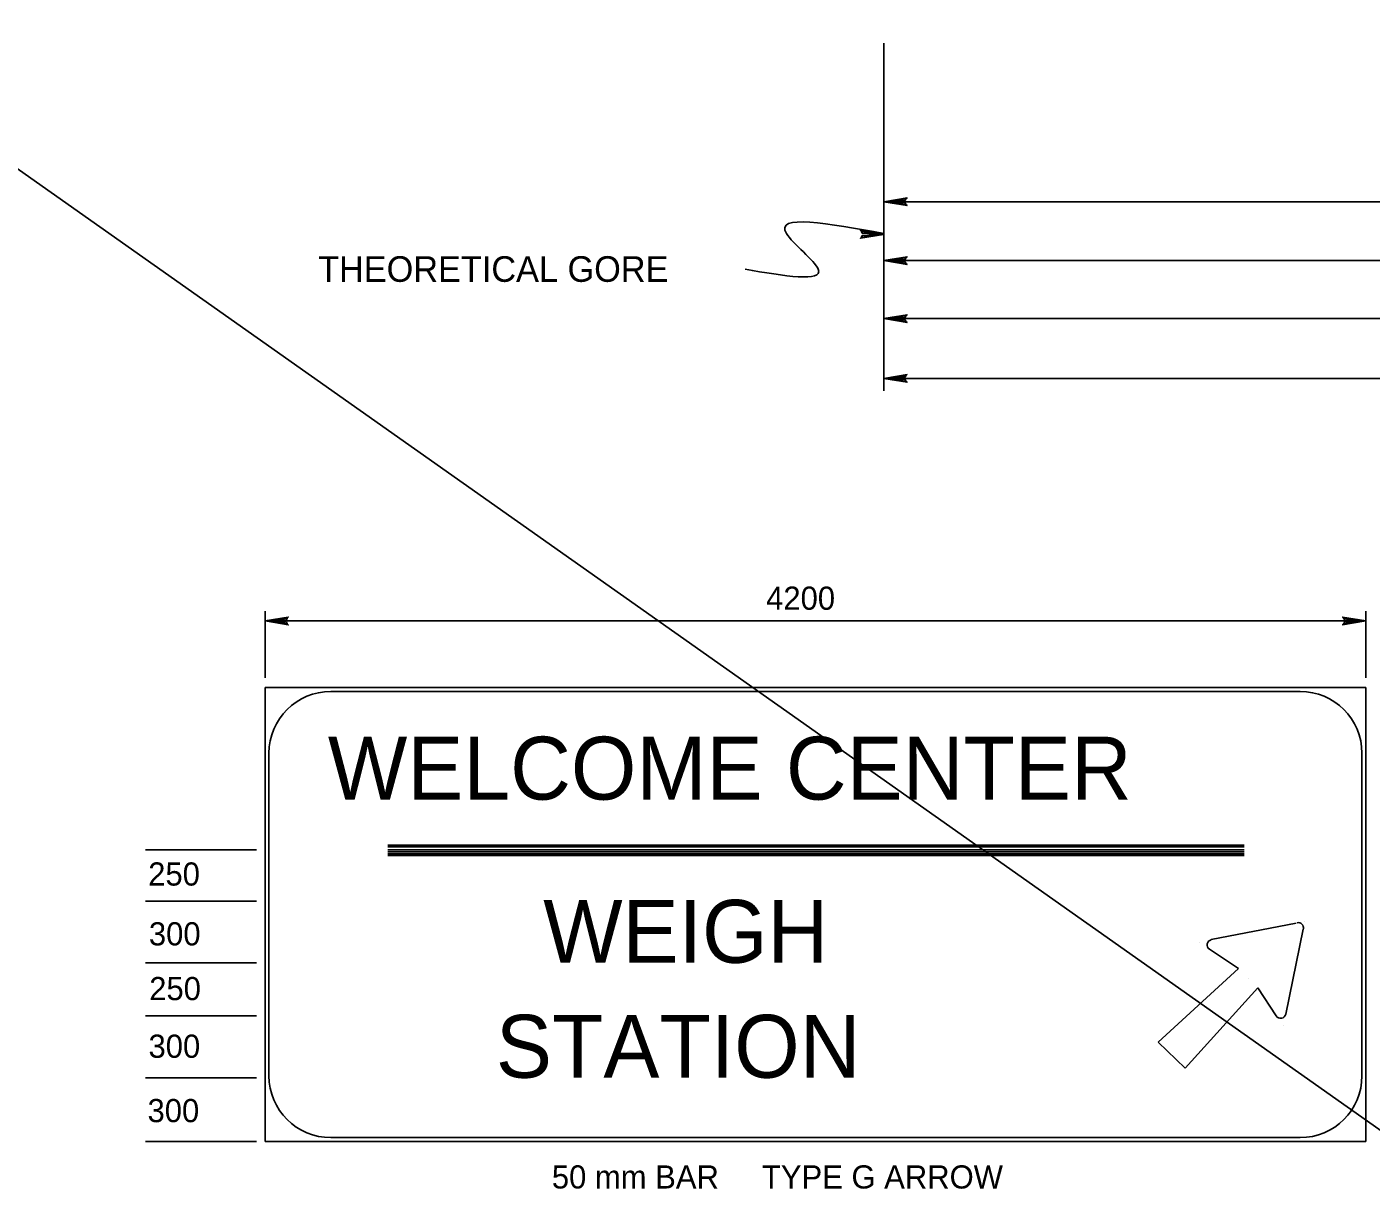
# Model space of a CAD drawing. Extents: x 2189973 to 2192941, y 2147557 to 2151454.
# Drawn here: x 2190575 to 2191146, y 2150594 to 2151094 of the extents above; entities that cross this region are included whole.
import ezdxf

# ---------------------------------------------------------------- set-up
doc = ezdxf.new("R2010")
doc.units = 0
doc.layers.add('1', color=7, linetype='Continuous')
doc.layers.add('Default', color=7, linetype='Continuous')

# ---------------------------------------------------------------- blocks, each defined once
blk = doc.blocks.new('RARROW')
at = {"layer": 'Default'}
blk.add_lwpolyline([(-18.156, 2.28), (-17.479, 0.966), (0, 0), (-18.156, 2.28), (-19.086, 3.077), (0, 0), (-17.465, -0.864), (-18.103, -2.164), (0, 0), (-19.086, -3.033), (-18.103, -2.164)], dxfattribs=at)

msp = doc.modelspace()

# ---------------------------------------------------------------- linework, layer by layer
at = {"layer": '1'}
msp.add_line((2190017.34, 2151423.79), (2192695.57, 2149534.55), dxfattribs=at)
at = {"layer": 'Default'}
for p, q in [((2190939.04, 2151086.55), (2190939.04, 2150938.91)), ((2191714.55, 2151019.29), (2190939.04, 2151019.29)), ((2190939.04, 2150994.27), (2192091.43, 2150994.27)), ((2192264.5, 2150969.67), (2190939.04, 2150969.67)), ((2192437.97, 2150944.24), (2190939.04, 2150944.24)), ((2190676.21, 2150817.04), (2190676.21, 2150845.34)), ((2191143.73, 2150817.04), (2191143.73, 2150845.34)), ((2190676.21, 2150841.24), (2191143.73, 2150841.24)), ((2190676.21, 2150812.94), (2191143.73, 2150812.94)), ((2190676.21, 2150812.94), (2190676.21, 2150620.19)), ((2191115.84, 2150811.3), (2190704.1, 2150811.3)), ((2191143.73, 2150620.19), (2191143.73, 2150812.94)), ((2190677.85, 2150785.05), (2190677.85, 2150648.08)), ((2191142.09, 2150648.08), (2191142.09, 2150785.05)), ((2190728.29, 2150746.09), (2191092.06, 2150746.09)), ((2190728.29, 2150745.27), (2191092.06, 2150745.27)), ((2190672.52, 2150744.04), (2190625.4, 2150744.04)), ((2190728.29, 2150744.04), (2191092.06, 2150744.04)), ((2190728.29, 2150743.22), (2191092.06, 2150743.22)), ((2190728.29, 2150742.4), (2191092.06, 2150742.4)), ((2190728.29, 2150741.58), (2191092.06, 2150741.58)), ((2190672.52, 2150722.31), (2190625.4, 2150722.31)), ((2191078.11, 2150705.9), (2191114.2, 2150712.88)), ((2191117.48, 2150713.7), (2191117.48, 2150713.7)), ((2191117.07, 2150710.42), (2191109.69, 2150674.33)), ((2191117.07, 2150710.42), (2191109.69, 2150674.33)), ((2191073.19, 2150704.67), (2191073.19, 2150704.67)), ((2191089.6, 2150693.6), (2191077.29, 2150701.8)), ((2191089.6, 2150693.6), (2191077.29, 2150701.8)), ((2190672.52, 2150696.06), (2190625.4, 2150696.06)), ((2191055.56, 2150662.43), (2191089.6, 2150693.6)), ((2191055.56, 2150662.43), (2191089.6, 2150693.6)), ((2191089.6, 2150693.6), (2191089.6, 2150693.6)), ((2191093.7, 2150689.5), (2191093.7, 2150689.5)), ((2191097.8, 2150685.4), (2191067.04, 2150651.36)), ((2191097.8, 2150685.4), (2191067.04, 2150651.36)), ((2191105.59, 2150673.51), (2191097.8, 2150685.4)), ((2191097.8, 2150685.4), (2191097.8, 2150685.4)), ((2190672.52, 2150673.51), (2190625.4, 2150673.51)), ((2191108.87, 2150669.41), (2191108.87, 2150669.41)), ((2191067.04, 2150651.36), (2191055.56, 2150662.43)), ((2191067.04, 2150651.36), (2191055.56, 2150662.43)), ((2191055.56, 2150662.43), (2191055.56, 2150662.43)), ((2191067.04, 2150651.36), (2191067.04, 2150651.36)), ((2190672.52, 2150647.26), (2190625.4, 2150647.26)), ((2190672.52, 2150620.19), (2190625.4, 2150620.19)), ((2191143.73, 2150620.19), (2190676.21, 2150620.19)), ((2190704.1, 2150621.83), (2191115.84, 2150621.83))]:
    msp.add_line(p, q, dxfattribs=at)
for centre, radius, start, end in [((2190704.1, 2150785.05), 26.25, 90, 180), ((2191115.84, 2150785.05), 26.25, 0, 90), ((2191115.02, 2150710.9), 2.25, 348.2602, 101.7398), ((2191115.02, 2150710.9), 2.25, 348.2602, 101.7398), ((2191078.52, 2150703.65), 2.21, 101.0564, 236.3099), ((2191107.51, 2150674.76), 2.25, 213.3162, 348.2602), ((2191107.51, 2150674.76), 2.25, 213.3162, 348.2602), ((2190704.1, 2150648.08), 26.25, 180, 270), ((2191115.84, 2150648.08), 26.25, 270, 0)]:
    msp.add_arc(centre, radius, start, end, dxfattribs=at)
msp.add_spline([(2190939.04, 2151005.76), (2190897.62, 2151005.76), (2190911.15, 2150990.58), (2190880.04, 2150990.58)], degree=3, dxfattribs=at)

# ---------------------------------------------------------------- block references
at = {"layer": 'Default', "xscale": 0.515679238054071, "yscale": 0.5369477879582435, "rotation": 180}
for p in [(2190939.04, 2151019.29), (2190939.04, 2150994.27), (2190939.04, 2150969.67), (2190939.04, 2150944.24), (2190676.21, 2150841.24)]:
    msp.add_blockref('RARROW', p, dxfattribs=at)
at = {"layer": 'Default', "xscale": 0.515679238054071, "yscale": 0.5369477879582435}
for p in [(2190938.87, 2151005.39), (2191143.73, 2150841.24)]:
    msp.add_blockref('RARROW', p, dxfattribs=at)

# ---------------------------------------------------------------- texts
at = {"layer": 'Default'}
for s, height, p in [('THEORETICAL GORE', 10.8833, (2190698.72, 2150985.25)), ('WELCOME CENTER', 26.7175, (2190702.87, 2150765.37)), ('WEIGH', 26.717, (2190794.32, 2150696.06)), ('STATION', 26.717, (2190774.22, 2150647.26))]:
    msp.add_text(s, height=height, rotation=360, dxfattribs=at).set_placement(p)
for s, height, p in [('4200', 9.842, (2190889.02, 2150845.99)), ('250', 9.842, (2190626.55, 2150728.87)), ('300', 9.842, (2190626.84, 2150703.46)), ('250', 9.842, (2190626.98, 2150680.21)), ('300', 9.842, (2190626.68, 2150655.73)), ('300', 9.842, (2190626.26, 2150628.39)), ('50 mm BAR     TYPE G ARROW', 9.8425, (2190798, 2150600.22))]:
    msp.add_text(s, height=height, dxfattribs=at).set_placement(p)

doc.saveas('drawing.dxf')
